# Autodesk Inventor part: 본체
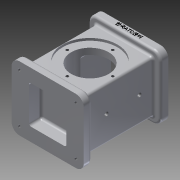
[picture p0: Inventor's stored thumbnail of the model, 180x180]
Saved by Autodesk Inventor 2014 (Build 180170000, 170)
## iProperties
Created: 2017-08
Part Number: 본체
Material: Aluminum 6061
Document SubType Name: Modeling
Designer: user
Density: 2.71 g/cm^3
Appearance: Aluminum - Flat
Mass: 871.497 g
Surface Area: 643.503 cm^2
Volume: 321.586 cm^3
Author: user
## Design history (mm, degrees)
sketch "Sketch2"
  geometry: L1 (0, 0)-(92, 0); L2 (92, 0)-(92, 82); L3 (92, 82)-(0, 82); L4 (0, 82)-(0, 0)
  constraints: 8 end point, 2 parallel, 1 horizontal, 1 perpendicular
  dimensions: "d0" = 92 distance of L3.end L2.end; "d1" = 82 distance of L2.end L1.end
extrude "Extrusion1" new body sketch "Sketch2" distance "d2" = 10; taper "d3" = 0 deg
sketch "Sketch3"
  geometry: L1 (0, 0)-(-92, 0) reference; L2 (0, -82)-(0, 0) reference; L3 (-83, -74)-(-9, -74); L4 (-9, -74)-(-9, -8); L5 (-9, -8)-(-83, -8); L6 (-83, -8)-(-83, -74); L7 (-83, -74)-(-9, -8); L8 (-9, -74)-(-83, -8); 1 further point
  constraints: 12 end point, 2 midpoint, 2 parallel, 1 horizontal, 1 perpendicular
  dimensions: "d4" = 74 distance of L5.end L4.end; "d5" = 66 distance of L4.end L3.end; "d6" = 46 distance from line of L2 point (-46, -41); "d7" = 41 distance from line of L1 point (-46, -41)
extrude "Extrusion2" join sketch "Sketch3" distance "d8" = 88; taper "d9" = 0 deg
sketch "Sketch4"
  geometry: L1 (-83, -74)-(-83, -8) reference; L2 (-83, -8)-(-9, -8) reference; L3 (-9, -8)-(-9, -74) reference; L4 (-9, -74)-(-83, -74) reference; L5 (0, 0)-(-92, 0) reference; L6 (-92, 0)-(-92, -82) reference; L7 (-92, -82)-(0, -82) reference; L8 (0, -82)-(0, 0) reference; 1 further point
extrude "Extrusion3" join sketch "Sketch4" distance "d10" = 10; taper "d11" = 0 deg
sketch "Sketch5"
  geometry: L1 (74, 0)-(74, 88) reference; L2 (-9, -10)-(83, -10) reference; L3 (83, -10)-(83, 0) reference; L4 (-9, 0)-(83, 0) reference; L5 (-9, -10)-(-9, 0) reference; C1 r 35 at (37, 44); 1 further point
  constraints: 1 centre point
  dimensions: "d12" = 70 diameter of C1; "d13" = 54 distance from line of L2 C1.centre; "d14" = 37 distance from line of L1 C1.centre
extrude "Extrusion4" cut sketch "Sketch5" distance "d15" = 3; taper "d16" = 0 deg
sketch "Sketch6"
  geometry: C1 r 35 at (0, 0) reference; C2 r 24 at (0, 0); 1 further point
  constraints: 1 centre point, 1 coincident
  dimensions: "d17" = 48 diameter of C2
extrude "Extrusion5" cut sketch "Sketch6" stored distance "d18" = 8; taper "d19" = 0 deg
sketch "Sketch7"
  geometry: C1 r 24 at (37, 44) reference; C2 r 35 at (37, 44) reference; 1 further point
extrude "Extrusion6" cut sketch "Sketch7" distance "d20" = 3; taper "d21" = 0 deg
sketch "Sketch9"
  geometry: L1 (-92, -82)-(0, -82) reference; L2 (0, -82)-(0, 0) reference; L3 (-72, -67)-(-20, -67); L4 (-20, -67)-(-20, -15); L5 (-20, -15)-(-72, -15); L6 (-72, -15)-(-72, -67); L7 (-72, -67)-(-20, -15); L8 (-20, -67)-(-72, -15); 1 further point
  constraints: 12 end point, 2 midpoint, 2 parallel, 1 horizontal, 1 perpendicular
  dimensions: "d22" = 52 distance of L5.end L4.end; "d23" = 52 distance of L4.end L3.end; "d24" = 46 distance from line of L2 point (-46, -41); "d25" = 41 distance from line of L1 point (-46, -41)
extrude "Extrusion7" cut sketch "Sketch9" distance "d26" = 8; taper "d27" = 0 deg
sketch "Sketch10"
  geometry: L1 (-68, -63)-(-24, -63); L2 (-24, -63)-(-24, -19); L3 (-24, -19)-(-68, -19); L4 (-68, -19)-(-68, -63); L5 (-68, -63)-(-24, -19); L6 (-24, -63)-(-68, -19); L7 (-92, 0)-(-92, -82) reference; L8 (0, 0)-(-92, 0) reference; 1 further point
  constraints: 12 end point, 2 midpoint, 2 parallel, 1 horizontal, 1 perpendicular
  dimensions: "d28" = 44 distance of L3.end L2.end; "d29" = 44 distance of L2.end L1.end; "d30" = 46 distance from line of L7 point (-46, -41); "d31" = 41 distance from line of L8 point (-46, -41)
extrude "Extrusion8" cut sketch "Sketch10" distance "d32" = 74; taper "d33" = 0 deg
sketch "Sketch11"
  geometry: L1 (0, 82)-(0, 0) reference; L2 (-92, 82)-(0, 82) reference; L3 (-70, 17)-(-22, 17); L4 (-22, 17)-(-22, 65); L5 (-22, 65)-(-70, 65); L6 (-70, 65)-(-70, 17); L7 (-70, 17)-(-22, 65); L8 (-22, 17)-(-70, 65); 1 further point
  constraints: 12 end point, 2 midpoint, 2 parallel, 1 horizontal, 1 perpendicular
  dimensions: "d34" = 48 distance of L5.end L4.end; "d35" = 48 distance of L4.end L3.end; "d36" = 46 distance from line of L1 point (-46, 41); "d37" = 41 distance from line of L2 point (-46, 41)
extrude "Extrusion9" cut sketch "Sketch11" distance "d38" = 16; taper "d39" = 0 deg
sketch "Sketch12" dims "d40" = 58
  geometry: L1 (0, 0)-(0, 29); C1 r 35 at (0, 0) reference; 1 further point
  constraints: 2 end point, 1 coincident, 1 vertical, 1 vertical alignment, 2 other
hole "Hole1" sketch "Sketch12" at (0, 29) diameter "d41" = 3.459; stored, may be unused: countersink angle "d45" = 90 deg, drill point angle "d47" = 118 deg; dims "d42" = 4, "d43" = 4, "d44" = 2, "d46" = 6
pattern_circular "Circular Pattern1" dims angle "d49" = 360 deg
sketch "Sketch13"
  geometry: L1 (0, 10)-(92, 10) reference; L2 (0, 0)-(0, 10) reference; 2 further points
  constraints: 1 other
  dimensions: "d51" = 46 distance from line of point (46, 6) L2; "d52" = 4 distance from line of L1 point (46, 6)
emboss "Emboss1" sketch "Sketch13" dims "d0" = 92, "d1" = 82, "d53" = 0.5, "d54" = 0
sketch "Sketch14" dims "d55" = 58
  geometry: L1 (0, 0)-(0, 29); C1 r 35 at (0, 0) reference; 1 further point
  constraints: 2 end point, 1 coincident, 1 vertical, 1 vertical alignment, 2 other
hole "Hole2" sketch "Sketch14" at (0, 29) diameter "d56" = 3.459; stored, may be unused: countersink angle "d60" = 90 deg, drill point angle "d62" = 118 deg; dims "d57" = 4, "d58" = 4, "d59" = 2, "d61" = 6
pattern_circular "Circular Pattern2" dims angle "d64" = 360 deg
sketch "Sketch15"
  geometry: L1 (0, 0)-(-92, 0) reference; L2 (-92, 82)-(0, 82) reference; L3 (-92, 0)-(-92, 82) reference; 4 further points
  dimensions: "d66" = 72 distance of point (-10, 72) point (-82, 72); "d67" = 10 distance from line of L3 point (-82, 72); "d68" = 62 distance of point (-10, 10) point (-10, 72); "d69" = 10 distance from line of L2 point (-10, 72); "d70" = 0 vertical distance of point (-82, 72) point (-10, 72); "d71" = 0 horizontal distance of point (-10, 10) point (-10, 72); "d72" = 72 distance of point (-10, 10) point (-82, 10); "d73" = 10 distance from line of L1 point (-82, 10)
hole "Hole3" sketch "Sketch15" at (-82, 72), (-10, 72), (-10, 10), (-82, 10) diameter "d74" = 3.459; stored, may be unused: countersink angle "d78" = 90 deg, drill point angle "d80" = 118 deg; dims "d75" = 4, "d76" = 4, "d77" = 2, "d79" = 6
workplane "Work Plane1"
mirror "Mirror1"
sketch "Sketch16"
  geometry: L1 (66, 0)-(66, 88) reference; L2 (0, 88)-(66, 88) reference; L3 (-8, -10)-(74, -10) reference; C1 r 2.5 at (33, 28); C2 r 2.5 at (33, 70)
  constraints: 2 centre point
  dimensions: "d88" = 5 diameter of C1; "d89" = 5 diameter of C2; "d90" = 42 distance of C1.centre C2.centre; "d91" = 38 distance from line of L3 C1.centre; "d92" = 33 distance from line of L1 C1.centre; "d93" = 18 distance from line of L2 C2.centre
extrude "Extrusion10" cut sketch "Sketch16" stored distance "d94" = 16; taper "d95" = 0 deg
thread "Thread1" dims "d96" = 10, "d97" = 0
thread "Thread2" dims "d98" = 10, "d99" = 0
fillet "Fillet1" dims "d100" = 10
fillet "Fillet2" dims "d101" = 10
fillet "Fillet3" dims "d102" = 3
fillet "Fillet4" dims "d103" = 3
fillet "Fillet5" dims "d104" = 3
chamfer "Chamfer1" distance "d105" = 1; stored, may be unused: second distance "d106" = 2, angle "d107" = 45 deg
fillet "Fillet6" dims "d108" = 3
body "Solid1"
node "Projected Loop1"
node "Projected Loop2"
